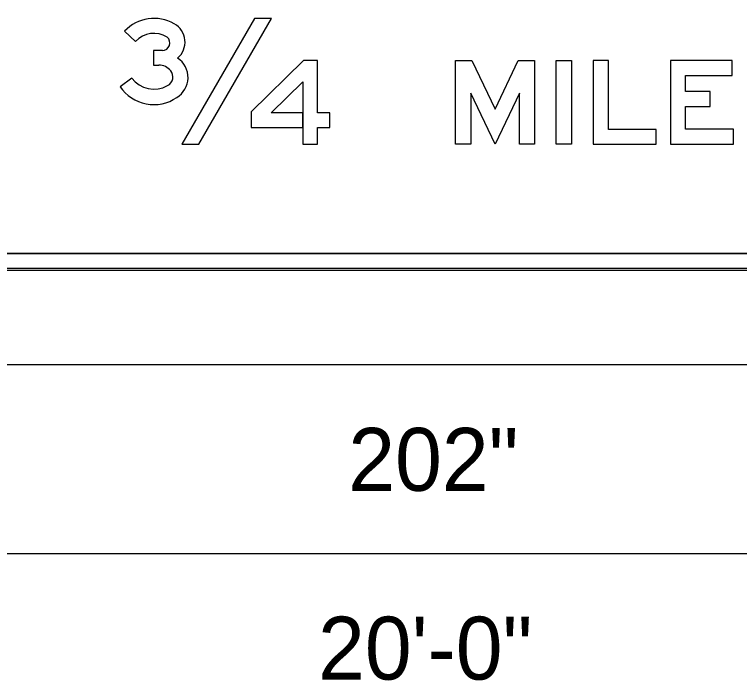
# Model space of a CAD drawing. Extents: x 1806251 to 1809821, y 414895 to 422886.
# Drawn here: x 1809677.104 to 1809677.968, y 415041.291 to 415042.085 of the extents above; entities that cross this region are included whole.
import ezdxf

# ---------------------------------------------------------------- set-up
doc = ezdxf.new("R2010")
doc.units = 0
for name, color, linetype in [('GSBWFILL', 7, 'Continuous'), ('GSCOLORFILL', 7, 'Continuous'), ('GSDIMS', 7, 'Continuous'), ('GSOUTLINE', 7, 'Continuous')]:
    doc.layers.add(name, color=color, linetype=linetype)

msp = doc.modelspace()

# ---------------------------------------------------------------- linework, layer by layer
at = {"layer": 'GSBWFILL'}
for p, q in [((1809677.2349, 415042.06495), (1809677.24792, 415042.05254)), ((1809677.26943, 415042.02449), (1809677.27591, 415042.02449)), ((1809677.2435, 415042.00898), (1809677.22964, 415041.99862)), ((1809678.67509, 415041.80007), (1809676.51529, 415041.80007)), ((1809676.51529, 415041.78007), (1809678.67509, 415041.78007))]:
    msp.add_line(p, q, dxfattribs=at)
for points in [[(1809677.30309, 415041.93007), (1809677.32329, 415041.93007), (1809677.4099, 415042.08007), (1809677.38969, 415042.08007)], [(1809677.4648, 415041.95004), (1809677.47939, 415041.95004), (1809677.47939, 415041.96754), (1809677.4648, 415041.96754), (1809677.4648, 415042.03007), (1809677.44817, 415042.03007), (1809677.38589, 415041.96856), (1809677.38589, 415041.95004), (1809677.4473, 415041.95004), (1809677.4473, 415041.96754), (1809677.40976, 415041.96754), (1809677.4473, 415042.00462), (1809677.4473, 415041.93007), (1809677.4648, 415041.93007)], [(1809677.67639, 415041.972), (1809677.704, 415042.03007), (1809677.72339, 415042.03007), (1809677.72339, 415041.93007), (1809677.70539, 415041.93007), (1809677.70539, 415041.99107), (1809677.67639, 415041.93007), (1809677.64739, 415041.99107), (1809677.64739, 415041.93007), (1809677.62939, 415041.93007), (1809677.62939, 415042.03007), (1809677.64878, 415042.03007)], [(1809677.74939, 415041.93007), (1809677.74939, 415042.03007), (1809677.76739, 415042.03007), (1809677.76739, 415041.93007)], [(1809677.86839, 415041.93007), (1809677.86839, 415041.94757), (1809677.81139, 415041.94757), (1809677.81139, 415042.03007), (1809677.79339, 415042.03007), (1809677.79339, 415041.93007)], [(1809677.96039, 415041.94807), (1809677.90339, 415041.94807), (1809677.90339, 415041.97497), (1809677.93289, 415041.97497), (1809677.93289, 415041.99297), (1809677.90339, 415041.99297), (1809677.90339, 415042.01207), (1809677.95889, 415042.01207), (1809677.95889, 415042.03007), (1809677.88539, 415042.03007), (1809677.88539, 415041.93007), (1809677.96039, 415041.93007)]]:
    msp.add_lwpolyline(points, close=True, dxfattribs=at)
msp.add_lwpolyline([(1809677.28002, 415042.04199), (1809677.26943, 415042.04199), (1809677.26943, 415042.02449)], dxfattribs=at)
for centre, major_axis, start_param, end_param in [((1809677.27015, 415042.03143), (0, 0.04864), 5.767147, 7.093801), ((1809677.28215, 415042.05191), (0, 0.02491), 3.838049, 5.780466), ((1809677.26992, 415042.03238), (0, 0.02983), 5.723665, 7.112147), ((1809677.28015, 415042.05083), (0, 0.00884), 3.12588, 5.597162), ((1809677.28292, 415042.00961), (0, 0.02773), 3.679655, 5.702579), ((1809677.27595, 415042.00672), (0, 0.01778), 5.377708, 6.285243), ((1809677.28109, 415042.01033), (0, 0.01151), 3.604962, 5.406296), ((1809677.26996, 415042.02884), (0, 0.03308), 2.214896, 3.655703), ((1809677.26976, 415042.02577), (0, 0.04844), 2.165865, 3.742074)]:
    msp.add_ellipse(centre, major_axis=major_axis, ratio=0.999998, start_param=start_param, end_param=end_param, dxfattribs=at)
at = {"layer": 'GSCOLORFILL'}
for p, q in [((1809677.2349, 415042.06495), (1809677.24792, 415042.05254)), ((1809677.26943, 415042.02449), (1809677.27591, 415042.02449)), ((1809677.2435, 415042.00898), (1809677.22964, 415041.99862)), ((1809678.67509, 415041.80007), (1809676.51529, 415041.80007)), ((1809676.51509, 415041.78007), (1809678.67509, 415041.78007)), ((1809678.67509, 415041.78207), (1809676.51511, 415041.78207)), ((1809676.51511, 415041.78007), (1809678.67509, 415041.78007)), ((1809676.51529, 415041.78007), (1809678.67509, 415041.78007))]:
    msp.add_line(p, q, dxfattribs=at)
for points in [[(1809677.30309, 415041.93007), (1809677.32329, 415041.93007), (1809677.4099, 415042.08007), (1809677.38969, 415042.08007)], [(1809677.4648, 415041.95004), (1809677.47939, 415041.95004), (1809677.47939, 415041.96754), (1809677.4648, 415041.96754), (1809677.4648, 415042.03007), (1809677.44817, 415042.03007), (1809677.38589, 415041.96856), (1809677.38589, 415041.95004), (1809677.4473, 415041.95004), (1809677.4473, 415041.96754), (1809677.40976, 415041.96754), (1809677.4473, 415042.00462), (1809677.4473, 415041.93007), (1809677.4648, 415041.93007)], [(1809677.67639, 415041.972), (1809677.704, 415042.03007), (1809677.72339, 415042.03007), (1809677.72339, 415041.93007), (1809677.70539, 415041.93007), (1809677.70539, 415041.99107), (1809677.67639, 415041.93007), (1809677.64739, 415041.99107), (1809677.64739, 415041.93007), (1809677.62939, 415041.93007), (1809677.62939, 415042.03007), (1809677.64878, 415042.03007)], [(1809677.74939, 415041.93007), (1809677.74939, 415042.03007), (1809677.76739, 415042.03007), (1809677.76739, 415041.93007)], [(1809677.86839, 415041.93007), (1809677.86839, 415041.94757), (1809677.81139, 415041.94757), (1809677.81139, 415042.03007), (1809677.79339, 415042.03007), (1809677.79339, 415041.93007)], [(1809677.96039, 415041.94807), (1809677.90339, 415041.94807), (1809677.90339, 415041.97497), (1809677.93289, 415041.97497), (1809677.93289, 415041.99297), (1809677.90339, 415041.99297), (1809677.90339, 415042.01207), (1809677.95889, 415042.01207), (1809677.95889, 415042.03007), (1809677.88539, 415042.03007), (1809677.88539, 415041.93007), (1809677.96039, 415041.93007)]]:
    msp.add_lwpolyline(points, close=True, dxfattribs=at)
msp.add_lwpolyline([(1809677.28002, 415042.04199), (1809677.26943, 415042.04199), (1809677.26943, 415042.02449)], dxfattribs=at)
for centre, major_axis, start_param, end_param in [((1809677.27015, 415042.03143), (0, 0.04864), 5.767147, 7.093801), ((1809677.28215, 415042.05191), (0, 0.02491), 3.838049, 5.780466), ((1809677.26992, 415042.03238), (0, 0.02983), 5.723665, 7.112147), ((1809677.28015, 415042.05083), (0, 0.00884), 3.12588, 5.597162), ((1809677.28292, 415042.00961), (0, 0.02773), 3.679655, 5.702579), ((1809677.27595, 415042.00672), (0, 0.01778), 5.377708, 6.285243), ((1809677.28109, 415042.01033), (0, 0.01151), 3.604962, 5.406296), ((1809677.26996, 415042.02884), (0, 0.03308), 2.214896, 3.655703), ((1809677.26976, 415042.02577), (0, 0.04844), 2.165865, 3.742074)]:
    msp.add_ellipse(centre, major_axis=major_axis, ratio=0.999998, start_param=start_param, end_param=end_param, dxfattribs=at)
at = {"layer": 'GSDIMS'}
for p, q in [((1809676.585, 415041.6675), (1809678.605, 415041.6675)), ((1809676.395, 415041.4425), (1809678.796, 415041.4425))]:
    msp.add_line(p, q, dxfattribs=at)
at = {"layer": 'GSOUTLINE'}
for p, q in [((1809677.2349, 415042.06495), (1809677.24792, 415042.05254)), ((1809677.26943, 415042.02449), (1809677.27591, 415042.02449)), ((1809677.2435, 415042.00898), (1809677.22964, 415041.99862)), ((1809676.51509, 415041.80007), (1809678.67509, 415041.80007)), ((1809676.51509, 415041.78007), (1809678.67509, 415041.78007))]:
    msp.add_line(p, q, dxfattribs=at)
for points in [[(1809677.30309, 415041.93007), (1809677.32329, 415041.93007), (1809677.4099, 415042.08007), (1809677.38969, 415042.08007)], [(1809677.4648, 415041.93007), (1809677.4648, 415041.95004), (1809677.47939, 415041.95004), (1809677.47939, 415041.96754), (1809677.4648, 415041.96754), (1809677.4648, 415042.03007), (1809677.44817, 415042.03007), (1809677.38589, 415041.96856), (1809677.38589, 415041.95004), (1809677.4473, 415041.95004), (1809677.4473, 415041.93007)], [(1809677.67639, 415041.972), (1809677.704, 415042.03007), (1809677.72339, 415042.03007), (1809677.72339, 415041.93007), (1809677.70539, 415041.93007), (1809677.70539, 415041.99107), (1809677.67639, 415041.93007), (1809677.64739, 415041.99107), (1809677.64739, 415041.93007), (1809677.62939, 415041.93007), (1809677.62939, 415042.03007), (1809677.64878, 415042.03007)], [(1809677.74939, 415041.93007), (1809677.74939, 415042.03007), (1809677.76739, 415042.03007), (1809677.76739, 415041.93007)], [(1809677.86839, 415041.93007), (1809677.86839, 415041.94757), (1809677.81139, 415041.94757), (1809677.81139, 415042.03007), (1809677.79339, 415042.03007), (1809677.79339, 415041.93007)], [(1809677.96039, 415041.94807), (1809677.90339, 415041.94807), (1809677.90339, 415041.97497), (1809677.93289, 415041.97497), (1809677.93289, 415041.99297), (1809677.90339, 415041.99297), (1809677.90339, 415042.01207), (1809677.95889, 415042.01207), (1809677.95889, 415042.03007), (1809677.88539, 415042.03007), (1809677.88539, 415041.93007), (1809677.96039, 415041.93007)], [(1809677.4473, 415041.96754), (1809677.40976, 415041.96754), (1809677.4473, 415042.00462)]]:
    msp.add_lwpolyline(points, close=True, dxfattribs=at)
msp.add_lwpolyline([(1809677.28002, 415042.04199), (1809677.26943, 415042.04199), (1809677.26943, 415042.02449)], dxfattribs=at)
for centre, major_axis, start_param, end_param in [((1809677.27015, 415042.03143), (0, 0.04864), 5.767147, 7.093801), ((1809677.28215, 415042.05191), (0, 0.02491), 3.838049, 5.780466), ((1809677.26992, 415042.03238), (0, 0.02983), 5.723665, 7.112147), ((1809677.28015, 415042.05083), (0, 0.00884), 3.12588, 5.597162), ((1809677.28292, 415042.00961), (0, 0.02773), 3.679655, 5.702579), ((1809677.27595, 415042.00672), (0, 0.01778), 5.377708, 6.285243), ((1809677.28109, 415042.01033), (0, 0.01151), 3.604962, 5.406296), ((1809677.26996, 415042.02884), (0, 0.03308), 2.214896, 3.655703), ((1809677.26976, 415042.02577), (0, 0.04844), 2.165865, 3.742074)]:
    msp.add_ellipse(centre, major_axis=major_axis, ratio=0.999998, start_param=start_param, end_param=end_param, dxfattribs=at)

# ---------------------------------------------------------------- texts
at = {"layer": 'GSDIMS'}
for s, p in [('202"', (1809677.5015, 415041.517)), ('20\'-0"', (1809677.4655, 415041.292))]:
    msp.add_text(s, height=0.075, dxfattribs=at).set_placement(p)

doc.saveas('drawing.dxf')
